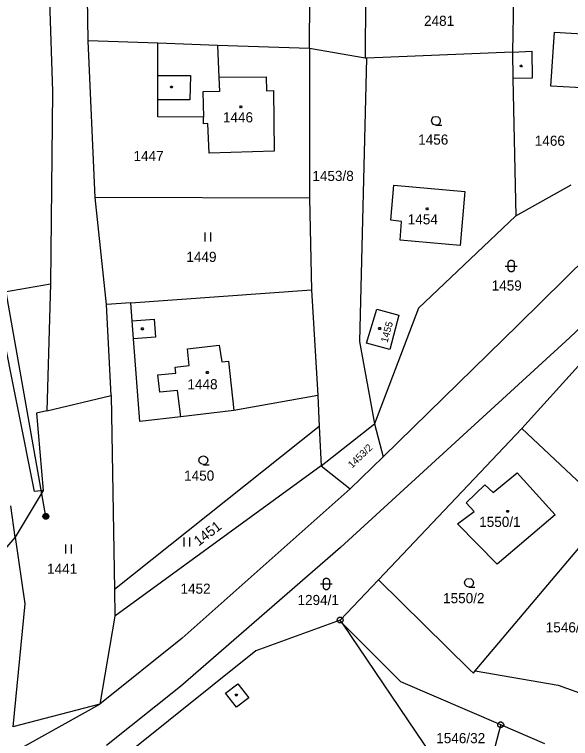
# Model space of a CAD drawing. Extents: x -609861 to -605046, y -1120287 to -1116307.
# Drawn here: x -606836.4 to -606743.1, y -1118876.3 to -1118754.8 of the extents above; entities that cross this region are included whole.
import ezdxf

# ---------------------------------------------------------------- set-up
doc = ezdxf.new("R2010")
doc.units = 0
for name, color, linetype in [('Vrstva 1', 7, 'Continuous'), ('Vrstva 2', 7, 'Continuous'), ('Vrstva 3', 7, 'Continuous'), ('Vrstva 4', 7, 'Continuous'), ('Vrstva 5', 7, 'Continuous'), ('Vrstva 6', 7, 'Continuous'), ('Vrstva 8', 7, 'Continuous')]:
    doc.layers.add(name, color=color, linetype=linetype)

msp = doc.modelspace()

# ---------------------------------------------------------------- linework, layer by layer
at = {"layer": 'Vrstva 1'}
for p, q in [((-606824.08, -1118759.23), (-606824.49, -1118725.63)), ((-606786.92, -1118760.52), (-606786.82, -1118727.3)), ((-606777.46, -1118746.05), (-606777.58, -1118762.11)), ((-606752.61, -1118747.57), (-606752.87, -1118761.13)), ((-606830.57, -1118752.52), (-606830.05, -1118767.71)), ((-606746.41, -1118766.85), (-606745.8, -1118757.78)), ((-606745.8, -1118757.78), (-606732.78, -1118758.49)), ((-606812.4, -1118759.64), (-606824.08, -1118759.23)), ((-606822.89, -1118785.51), (-606824.08, -1118759.23)), ((-606802.38, -1118759.99), (-606812.4, -1118759.64)), ((-606812.4, -1118765.03), (-606812.4, -1118759.64)), ((-606786.92, -1118760.52), (-606802.38, -1118759.99)), ((-606802.38, -1118759.99), (-606802.15, -1118765.33)), ((-606786.92, -1118760.52), (-606786.95, -1118785.64)), ((-606777.58, -1118762.11), (-606786.92, -1118760.52)), ((-606752.87, -1118761.13), (-606777.36, -1118762.15)), ((-606752.87, -1118761.13), (-606752.81, -1118765.52)), ((-606777.36, -1118762.15), (-606778.54, -1118809.66)), ((-606777.36, -1118762.15), (-606777.58, -1118762.11)), ((-606812.4, -1118769.1), (-606812.4, -1118765.03)), ((-606802.15, -1118765.33), (-606794.18, -1118765.27)), ((-606794.18, -1118765.27), (-606794.14, -1118767.6)), ((-606752.81, -1118765.52), (-606752.27, -1118788.61)), ((-606794.14, -1118767.6), (-606792.94, -1118767.58)), ((-606792.94, -1118767.58), (-606792.86, -1118777.72)), ((-606733.32, -1118767.58), (-606746.41, -1118766.85)), ((-606830.05, -1118767.71), (-606830.4, -1118799.98)), ((-606812.4, -1118772), (-606812.4, -1118769.1)), ((-606804.72, -1118772.02), (-606812.4, -1118772)), ((-606804.7, -1118773.13), (-606804.72, -1118772.02)), ((-606803.97, -1118773.12), (-606804.7, -1118773.13)), ((-606803.75, -1118778.07), (-606803.97, -1118773.12)), ((-606718.37, -1118773.62), (-606751.84, -1118806.84)), ((-606792.86, -1118777.72), (-606803.75, -1118778.07)), ((-606714.64, -1118781.57), (-606743.22, -1118809.02)), ((-606752.27, -1118788.61), (-606743.02, -1118783.41)), ((-606773.27, -1118789.31), (-606772.75, -1118783.47)), ((-606772.75, -1118783.47), (-606760.83, -1118784.52)), ((-606760.83, -1118784.52), (-606761.63, -1118793.58)), ((-606786.95, -1118785.64), (-606822.89, -1118785.51)), ((-606821, -1118803.47), (-606822.89, -1118785.51)), ((-606786.95, -1118785.64), (-606786.59, -1118800.99)), ((-606771.5, -1118789.54), (-606773.27, -1118789.31)), ((-606752.27, -1118788.61), (-606768.66, -1118804.09)), ((-606751.28, -1118824.26), (-606719.97, -1118789.52)), ((-606771.73, -1118792.7), (-606771.5, -1118789.54)), ((-606761.63, -1118793.58), (-606771.73, -1118792.7)), ((-606838.12, -1118801.33), (-606830.4, -1118799.98)), ((-606830.4, -1118799.98), (-606830.99, -1118821.29)), ((-606816.9, -1118803.17), (-606786.59, -1118800.99)), ((-606786.59, -1118800.99), (-606785.53, -1118818.74)), ((-606816.9, -1118803.17), (-606821, -1118803.47)), ((-606820.2, -1118818.73), (-606821, -1118803.47)), ((-606816.69, -1118806.2), (-606816.9, -1118803.17)), ((-606768.66, -1118804.09), (-606775.99, -1118823.5)), ((-606777.35, -1118809.96), (-606775.64, -1118804.25)), ((-606775.64, -1118804.25), (-606771.95, -1118805.28)), ((-606771.95, -1118805.28), (-606773.47, -1118811)), ((-606833.05, -1118834.87), (-606838.71, -1118806.46)), ((-606816.47, -1118809.21), (-606816.69, -1118806.2)), ((-606751.84, -1118806.84), (-606774.54, -1118829.04)), ((-606815.39, -1118823.11), (-606816.47, -1118809.21)), ((-606743.22, -1118809.02), (-606781.74, -1118844.22)), ((-606778.54, -1118809.66), (-606775.99, -1118823.5)), ((-606773.47, -1118811), (-606777.35, -1118809.96)), ((-606830.99, -1118821.29), (-606820.2, -1118818.73)), ((-606820.2, -1118818.73), (-606819.67, -1118851.27)), ((-606785.53, -1118818.74), (-606799.65, -1118821.23)), ((-606785.53, -1118818.74), (-606785.28, -1118823.96)), ((-606830.99, -1118821.29), (-606832.74, -1118821.72)), ((-606832.74, -1118821.72), (-606831.6, -1118834.67)), ((-606799.65, -1118821.23), (-606808.52, -1118822.34)), ((-606808.52, -1118822.34), (-606815.39, -1118823.11)), ((-606784.98, -1118830.55), (-606775.99, -1118823.5)), ((-606775.99, -1118823.5), (-606774.54, -1118829.04)), ((-606785.28, -1118823.96), (-606819.67, -1118851.27)), ((-606785.28, -1118823.96), (-606784.98, -1118830.55)), ((-606751.28, -1118824.26), (-606775.36, -1118849.66)), ((-606736.55, -1118838.17), (-606751.28, -1118824.26)), ((-606774.54, -1118829.04), (-606780.08, -1118834.42)), ((-606784.98, -1118830.55), (-606819.6, -1118855.77)), ((-606784.98, -1118830.55), (-606780.08, -1118834.42)), ((-606756.08, -1118835.02), (-606752.09, -1118831.74)), ((-606752.09, -1118831.74), (-606745.68, -1118838.78)), ((-606780.08, -1118834.42), (-606808.31, -1118859.48)), ((-606760.61, -1118836.75), (-606757.52, -1118833.73)), ((-606757.52, -1118833.73), (-606756.08, -1118835.02)), ((-606831.6, -1118834.67), (-606836.3, -1118842.49)), ((-606831.6, -1118834.67), (-606833.05, -1118834.87)), ((-606759.3, -1118838.19), (-606760.61, -1118836.75)), ((-606836.3, -1118842.49), (-606837.02, -1118837.25)), ((-606762.11, -1118840.28), (-606759.3, -1118838.19)), ((-606759.1, -1118864.93), (-606736.55, -1118838.17)), ((-606745.68, -1118838.78), (-606755.44, -1118847.06)), ((-606755.44, -1118847.06), (-606762.11, -1118840.28)), ((-606836.3, -1118842.49), (-606839.23, -1118845.8)), ((-606836.3, -1118842.49), (-606834.67, -1118853.68)), ((-606781.74, -1118844.22), (-606808.6, -1118867.55)), ((-606775.36, -1118849.66), (-606781.77, -1118856.42)), ((-606775.36, -1118849.66), (-606760.04, -1118864.77)), ((-606819.67, -1118851.27), (-606819.6, -1118855.77)), ((-606834.67, -1118853.68), (-606836.7, -1118874.35)), ((-606819.6, -1118855.77), (-606822.1, -1118870.53)), ((-606781.77, -1118856.42), (-606795.91, -1118861.56)), ((-606781.43, -1118856.93), (-606781.77, -1118856.42)), ((-606781.43, -1118856.93), (-606753.14, -1118898.82)), ((-606771.58, -1118866.78), (-606781.43, -1118856.93)), ((-606808.31, -1118859.48), (-606822.1, -1118870.53)), ((-606795.91, -1118861.56), (-606825.86, -1118885.54)), ((-606760.04, -1118864.77), (-606759.43, -1118865.32)), ((-606759.43, -1118865.32), (-606759.1, -1118864.93)), ((-606759.1, -1118864.93), (-606745.17, -1118867.33)), ((-606754.83, -1118874), (-606771.58, -1118866.78)), ((-606808.6, -1118867.55), (-606821.02, -1118877.44)), ((-606745.17, -1118867.33), (-606737.94, -1118869.96)), ((-606822.1, -1118870.53), (-606836.7, -1118874.35)), ((-606747.42, -1118877.2), (-606754.83, -1118874))]:
    msp.add_line(p, q, dxfattribs=at)
msp.add_lwpolyline([(-606754.83, -1118874), (-606755.14, -1118875.16), (-606757.18, -1118882.88), (-606749.46, -1118884.92)], dxfattribs=at)
at = {"layer": 'Vrstva 3'}
for p, q in [((-606804.48, -1118791.4), (-606804.48, -1118792.9)), ((-606803.48, -1118792.9), (-606803.48, -1118791.4)), ((-606807.99, -1118842.57), (-606807.99, -1118844.07)), ((-606806.99, -1118844.07), (-606806.99, -1118842.57)), ((-606827.86, -1118843.74), (-606827.86, -1118845.24)), ((-606826.86, -1118845.24), (-606826.86, -1118843.74))]:
    msp.add_line(p, q, dxfattribs=at)
for points in [[(-606765.71, -1118773.38), (-606766.09, -1118773.28), (-606766.36, -1118773.01), (-606766.46, -1118772.64), (-606766.36, -1118772.27), (-606766.09, -1118772), (-606765.72, -1118771.9), (-606765.35, -1118772), (-606765.08, -1118772.27), (-606764.98, -1118772.65), (-606765.08, -1118773.03), (-606765.35, -1118773.3), (-606765.73, -1118773.4), (-606764.73, -1118773.4)], [(-606754.07, -1118797.01), (-606752.8, -1118797.01), (-606752.07, -1118797.01)], [(-606804.72, -1118830.33), (-606805.1, -1118830.23), (-606805.37, -1118829.96), (-606805.47, -1118829.59), (-606805.37, -1118829.22), (-606805.1, -1118828.95), (-606804.73, -1118828.85), (-606804.36, -1118828.95), (-606804.09, -1118829.22), (-606803.99, -1118829.6), (-606804.09, -1118829.98), (-606804.36, -1118830.25), (-606804.74, -1118830.35), (-606803.74, -1118830.35)], [(-606760.15, -1118850.9), (-606760.53, -1118850.8), (-606760.8, -1118850.53), (-606760.9, -1118850.16), (-606760.8, -1118849.79), (-606760.53, -1118849.52), (-606760.16, -1118849.42), (-606759.79, -1118849.52), (-606759.52, -1118849.79), (-606759.42, -1118850.17), (-606759.52, -1118850.55), (-606759.79, -1118850.82), (-606760.17, -1118850.92), (-606759.17, -1118850.92)], [(-606785.1, -1118850.35), (-606783.83, -1118850.35), (-606783.1, -1118850.35)]]:
    msp.add_lwpolyline(points, dxfattribs=at)
for points in [[(-606753.57, -1118796.51), (-606753.47, -1118796.22), (-606753.22, -1118796.04), (-606752.91, -1118796.04), (-606752.66, -1118796.22), (-606752.56, -1118796.51), (-606752.56, -1118797.51), (-606752.66, -1118797.8), (-606752.91, -1118797.98), (-606753.22, -1118797.98), (-606753.47, -1118797.8), (-606753.57, -1118797.51)], [(-606784.6, -1118849.85), (-606784.5, -1118849.56), (-606784.25, -1118849.38), (-606783.94, -1118849.38), (-606783.69, -1118849.56), (-606783.59, -1118849.85), (-606783.59, -1118850.85), (-606783.69, -1118851.14), (-606783.94, -1118851.32), (-606784.25, -1118851.32), (-606784.5, -1118851.14), (-606784.6, -1118850.85)]]:
    msp.add_lwpolyline(points, close=True, dxfattribs=at)
at = {"layer": 'Vrstva 4'}
for p, q in [((-606752.87, -1118761.13), (-606749.61, -1118760.98)), ((-606749.61, -1118760.98), (-606749.57, -1118765.49)), ((-606812.4, -1118765.03), (-606806.87, -1118765.02)), ((-606806.87, -1118765.02), (-606806.99, -1118769.15)), ((-606802.15, -1118765.33), (-606802.05, -1118767.75)), ((-606749.57, -1118765.49), (-606752.81, -1118765.52)), ((-606802.05, -1118767.75), (-606804.8, -1118767.77)), ((-606804.8, -1118767.77), (-606804.72, -1118772.02)), ((-606806.99, -1118769.15), (-606812.4, -1118769.1)), ((-606816.69, -1118806.2), (-606813.01, -1118805.94)), ((-606813.01, -1118805.94), (-606812.79, -1118808.95)), ((-606812.79, -1118808.95), (-606816.47, -1118809.21)), ((-606807.42, -1118810.92), (-606802.08, -1118810.28)), ((-606807.1, -1118813.71), (-606807.42, -1118810.92)), ((-606802.08, -1118810.28), (-606801.64, -1118813.07)), ((-606809.48, -1118814), (-606807.1, -1118813.71)), ((-606801.64, -1118813.07), (-606800.52, -1118812.97)), ((-606800.52, -1118812.97), (-606799.65, -1118821.23)), ((-606812.36, -1118815.25), (-606809.35, -1118814.98)), ((-606809.35, -1118814.98), (-606809.48, -1118814)), ((-606812.05, -1118818.17), (-606812.36, -1118815.25)), ((-606809.08, -1118817.89), (-606812.05, -1118818.17)), ((-606808.52, -1118822.34), (-606809.08, -1118817.89)), ((-606801.01, -1118868.67), (-606798.97, -1118867.11)), ((-606798.97, -1118867.11), (-606797.12, -1118869.49)), ((-606799.16, -1118871.06), (-606801.01, -1118868.67)), ((-606797.12, -1118869.49), (-606799.16, -1118871.06)), ((-606847.19, -1118884.44), (-606822.1, -1118870.53))]:
    msp.add_line(p, q, dxfattribs=at)
at = {"layer": 'Vrstva 5'}
for points in [[(-606751.32, -1118763.29), (-606751.23, -1118763.44), (-606751.32, -1118763.59), (-606751.5, -1118763.59), (-606751.59, -1118763.44), (-606751.5, -1118763.29)], [(-606809.99, -1118766.82), (-606809.9, -1118766.97), (-606809.99, -1118767.12), (-606810.17, -1118767.12), (-606810.26, -1118766.97), (-606810.17, -1118766.82)], [(-606798.35, -1118770.15), (-606798.26, -1118770.3), (-606798.35, -1118770.45), (-606798.53, -1118770.45), (-606798.62, -1118770.3), (-606798.53, -1118770.15)], [(-606767.1, -1118787.27), (-606767.01, -1118787.42), (-606767.1, -1118787.57), (-606767.28, -1118787.57), (-606767.37, -1118787.42), (-606767.28, -1118787.27)], [(-606814.89, -1118807.41), (-606814.8, -1118807.56), (-606814.89, -1118807.71), (-606815.07, -1118807.71), (-606815.16, -1118807.56), (-606815.07, -1118807.41)], [(-606775.06, -1118807.35), (-606774.97, -1118807.5), (-606775.06, -1118807.65), (-606775.24, -1118807.65), (-606775.33, -1118807.5), (-606775.24, -1118807.35)], [(-606803.99, -1118814.72), (-606803.9, -1118814.87), (-606803.99, -1118815.02), (-606804.17, -1118815.02), (-606804.26, -1118814.87), (-606804.17, -1118814.72)], [(-606753.57, -1118838.04), (-606753.48, -1118838.19), (-606753.57, -1118838.34), (-606753.75, -1118838.34), (-606753.84, -1118838.19), (-606753.75, -1118838.04)], [(-606799.11, -1118868.86), (-606799.02, -1118869.01), (-606799.11, -1118869.16), (-606799.29, -1118869.16), (-606799.38, -1118869.01), (-606799.29, -1118868.86)]]:
    msp.add_lwpolyline(points, close=True, dxfattribs=at)
at = {"layer": 'Vrstva 6'}
msp.add_line((-606831.18, -1118839.03), (-606838.1, -1118799.79), dxfattribs=at)
msp.add_lwpolyline([(-606831.33, -1118838.55), (-606831.02, -1118838.55), (-606830.77, -1118838.73), (-606830.67, -1118839.02), (-606830.77, -1118839.31), (-606831.02, -1118839.49), (-606831.33, -1118839.49), (-606831.58, -1118839.31), (-606831.68, -1118839.02), (-606831.58, -1118838.73), (-606831.33, -1118838.55), (-606831.3, -1118838.59), (-606831.06, -1118838.59), (-606830.9, -1118838.67), (-606831.46, -1118838.67), (-606831.54, -1118838.75), (-606830.82, -1118838.75), (-606830.82, -1118838.83), (-606831.54, -1118838.83), (-606831.58, -1118838.91), (-606830.78, -1118838.91), (-606830.74, -1118838.99), (-606831.62, -1118838.99), (-606831.62, -1118839.07), (-606830.74, -1118839.07), (-606830.77, -1118839.15), (-606831.58, -1118839.15), (-606831.57, -1118839.23), (-606830.76, -1118839.23), (-606830.81, -1118839.31), (-606831.53, -1118839.31), (-606831.45, -1118839.39), (-606830.89, -1118839.39), (-606831, -1118839.47), (-606831.34, -1118839.47)], dxfattribs=at)
at = {"layer": 'Vrstva 8'}
for p, q in [((-606781.89, -1118856.42), (-606781.65, -1118856.42)), ((-606754.95, -1118874), (-606754.71, -1118874))]:
    msp.add_line(p, q, dxfattribs=at)
for points in [[(-606781.62, -1118855.94), (-606781.37, -1118856.12), (-606781.27, -1118856.41), (-606781.37, -1118856.7), (-606781.62, -1118856.88), (-606781.93, -1118856.88), (-606782.18, -1118856.7), (-606782.28, -1118856.41), (-606782.18, -1118856.12), (-606781.93, -1118855.94)], [(-606754.68, -1118873.52), (-606754.43, -1118873.7), (-606754.33, -1118873.99), (-606754.43, -1118874.28), (-606754.68, -1118874.46), (-606754.99, -1118874.46), (-606755.24, -1118874.28), (-606755.34, -1118873.99), (-606755.24, -1118873.7), (-606754.99, -1118873.52)]]:
    msp.add_lwpolyline(points, close=True, dxfattribs=at)

# ---------------------------------------------------------------- texts
at = {"layer": 'Vrstva 2'}
for s, p in [('2481', (-606767.703, -1118756.71)), ('1446', (-606801.457, -1118772.91)), ('1456', (-606768.687, -1118776.64)), ('1466', (-606749.117, -1118776.84)), ('1447', (-606816.457, -1118779.39)), ('1453/8', (-606786.448, -1118782.74)), ('1454', (-606770.437, -1118790.02)), ('1449', (-606807.587, -1118796.32)), ('1459', (-606756.357, -1118801.13)), ('1448', (-606807.407, -1118817.7)), ('1450', (-606807.967, -1118833.03)), ('1550/1', (-606758.447, -1118840.79)), ('1441', (-606830.967, -1118848.66)), ('1452', (-606808.577, -1118852)), ('1294/1', (-606788.937, -1118853.9)), ('1550/2', (-606764.507, -1118853.59)), ('1546/2', (-606747.277, -1118858.49)), ('1546/32', (-606765.657, -1118877.08))]:
    msp.add_text(s, height=1.7, dxfattribs=at).set_placement(p)
for s, height, rotation, p in [('1455', 1.2, 74.7137, (-606773.837, -1118809.953)), ('1453/2', 1.2, 44.11775, (-606779.771, -1118831.027)), ('1451', 1.7, 37.81521, (-606805.52, -1118844.089))]:
    msp.add_text(s, height=height, rotation=rotation, dxfattribs=at).set_placement(p)

doc.saveas('drawing.dxf')
